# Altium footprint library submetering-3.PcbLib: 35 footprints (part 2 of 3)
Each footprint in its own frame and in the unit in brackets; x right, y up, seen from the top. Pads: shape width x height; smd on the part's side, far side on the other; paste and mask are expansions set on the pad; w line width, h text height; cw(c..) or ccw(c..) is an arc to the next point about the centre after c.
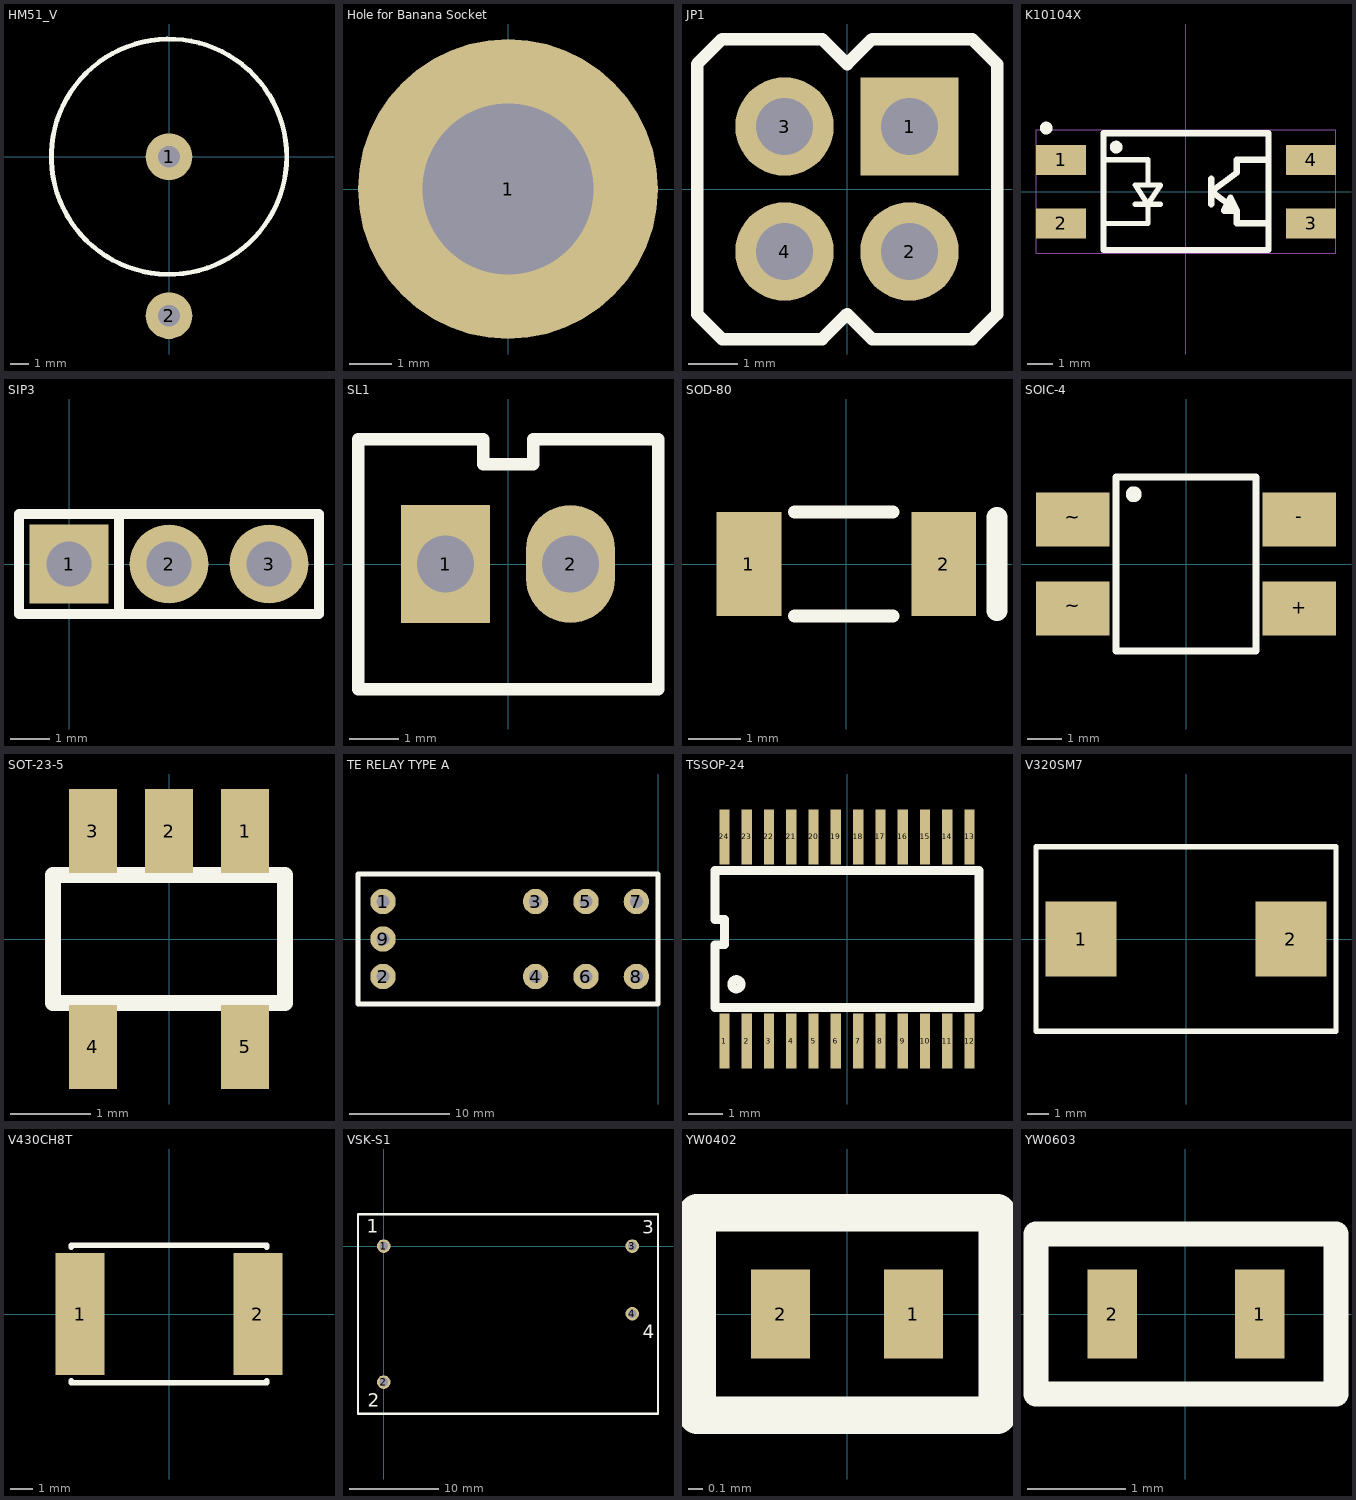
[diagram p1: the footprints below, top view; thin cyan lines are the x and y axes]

## HM51_V [mm] "HM51 Insductors (vertical)"
pads (2):
  round 2.5 hole 1.15: 1(0,0) 2(0,-8.5)
TopOverlay:
  circle w0.254: c0,0 r6.294

## Hole for Banana Socket [mm] "Hole for Banana Socket"
pads (1):
  round 7 hole 4: 1(0,0)

## JP1 [mm]
pads (4):
  rect 2x2 hole 1.15: 1(1.27,1.27)
  round 2 hole 1.15: 2(1.27,-1.27) 3(-1.27,1.27) 4(-1.27,-1.27)
TopOverlay:
  lines w0.254: -3.048,-2.54 -3.048,2.54 -2.54,3.048 -0.508,3.048 0,2.54 0.508,3.048 2.54,3.048 3.048,2.54 3.048,-2.54 2.54,-3.048 0.508,-3.048 0,-2.54 -0.508,-3.048 -2.54,-3.048 -3.048,-2.54

## K10104X [mm] "K10104X"
pads (4):
  rect 2x1.2 smd: 1(-4.997,1.283) 2(-4.997,-1.257) 3(5.003,-1.257) 4(5.003,1.283)
TopOverlay:
  circle w0.254: c-5.585,2.553 r0.127
  circle w0.254: c-2.791,1.791 r0.127
  lines w0.203: -3.299,-1.257 -1.521,-1.257 -1.521,-0.495 ; -3.299,1.283 -1.521,1.283 -1.521,0.267 ; -2.029,-0.495 -1.013,-0.495 ; -1.521,-0.495 -1.013,0.267 -2.029,0.267 -1.521,-0.495
  lines w0.254: 1.019,-0.495 1.019,0.521 ; 3.305,-1.257 2.035,-1.257 2.035,-0.749 ; 3.305,1.283 2.035,1.283 2.035,0.775 1.019,0.013 2.035,-0.749 ; 2.035,-0.749 1.781,-0.241 1.527,-0.749 2.035,-0.749 ; -3.299,-2.324 3.305,-2.324 3.305,2.349 -3.299,2.349 -3.299,-2.324
Mechanical 18:
  lines w0.025: -5.991,-2.451 5.998,-2.451 5.998,2.476 -5.991,2.476 -5.991,-2.451

## SIP3 [mm]
pads (3):
  rect 2x2 hole 1.15: 1(0,0)
  round 2 hole 1.15: 2(2.54,0) 3(5.08,0)
TopOverlay:
  lines w0.254: 1.27,-1.27 1.27,1.27 ; -1.27,-1.27 6.35,-1.27 6.35,1.27 -1.27,1.27 -1.27,-1.27

## SL1 [mm]
pads (2):
  rect 1.8x2.4 hole 1.15: 1(-1.27,0)
  oval 1.8x2.4 hole 1.15: 2(1.27,0)
TopOverlay:
  lines w0.254: -3.048,-2.54 3.048,-2.54 3.048,2.032 3.048,2.54 0.508,2.54 0.508,2.032 -0.508,2.032 -0.508,2.54 -3.048,2.54 -3.048,2.032 -3.048,-2.54

## SOD-80 [mm]
pads (2):
  rect 1.25x2 smd: 1(-1.875,0) 2(1.875,0)
TopOverlay:
  lines w0.254: -1,-1 0.9,-1 ; -1,1 0.9,1
  lines w0.4: 2.9,-0.9 2.9,0.9
3D body: height 0.69, standoff -0.7, extent -1.28,-0.697 1.28,0.7
3D body: height 0.79, standoff -0.8, extent 1.28,-0.8 1.75,0.797
3D body: height 0.79, standoff -0.8, extent -1.7,-0.798 -1.23,0.798
3D body: height 0.69, standoff -0.7, extent 1,-0.697 1.2,0.7

## SOIC-4 [mm] "SOIC-4"
height 2.65
pads (4):
  rect 2.1x1.55 smd: +(3.25,-1.27) -(3.25,1.27) ~(-3.25,-1.27) ~(-3.25,1.27)
TopOverlay:
  circle w0.254: c-1.5,2 r0.1
  lines w0.2: -2,-2.5 2,-2.5 2,2.5 -2,2.5 -2,0 -2,-2.5

## SOT-23-5 [mm]
pads (5):
  rect 0.6x1.05 smd: 1(0.95,1.35) 2(0,1.35) 3(-0.95,1.35) 4(-0.95,-1.35) 5(0.95,-1.35)
TopOverlay:
  lines w0.203: -1.45,-0.8 1.45,-0.8 1.45,0.8 -1.45,0.8 -1.45,-0.8

## TE RELAY TYPE A [mm] "TE Relay type A footprint"
height 15.7
pads (9):
  round 2.54 hole 1.3: 1(-27.5,3.75) 2(-27.5,-3.75) 3(-12.24,3.75) 4(-12.24,-3.75) 5(-7.2,3.75) 6(-7.2,-3.75) 7(-2.16,3.75) 8(-2.16,-3.75) 9(-27.5,0)
TopOverlay:
  lines w0.5: -30,-6.5 -30,6.5 0,6.5 0,-6.5 -30,-6.5
Mechanical5:
  text ".Designator" at -23.6,-0.5 h1.02
3D body: height 15.7, standoff 0, extent -30.25,-6.75 0.25,6.75
3D body: height 15.7, standoff 0, extent -29.999,-6.499 -0.001,6.499
3D body: height 15.7, standoff 0, extent -30.25,-6.75 0.25,6.75
3D body: height 15.7, standoff 0, extent -28.872,-5.122 -0.788,5.122

## TSSOP-24 [mm] "TSSOP-24 (IPW)"
pads (24):
  rect 0.3x1.6 smd: 1(-3.575,-2.98) 2(-2.925,-2.98) 3(-2.275,-2.98) 4(-1.625,-2.98) 5(-0.975,-2.98) 6(-0.325,-2.98) 7(0.325,-2.98) 8(0.975,-2.98) 9(1.625,-2.98) 10(2.275,-2.98) 11(2.925,-2.98) 12(3.575,-2.98) 13(3.575,2.98) 14(2.925,2.98) 15(2.275,2.98) 16(1.625,2.98) 17(0.975,2.98) 18(0.325,2.98) 19(-0.325,2.98) 20(-0.975,2.98) 21(-1.625,2.98) 22(-2.275,2.98) 23(-2.925,2.98) 24(-3.575,2.98)
TopOverlay:
  circle w0.254: c-3.226,-1.321 r0.137
  lines w0.254: -3.85,-2 -3.85,-0.167 -3.571,-0.167 -3.571,0.57 -3.85,0.57 -3.85,2 3.85,2 3.85,-2 -3.85,-2

## V320SM7 [mm] "SMD MOV"
height 6
pads (2):
  rect 3.3x3.5 smd: 1(-4.9,0) 2(4.9,0)
TopOverlay:
  lines w0.254: -7,-4.3 -7,4.3 7,4.3 7,-4.3 -7,-4.3
3D body: height 6, standoff 0.3, extent -5.7,-4.1 5.7,4
3D body: height 3, standoff 0, extent -6,-1.5 -5.7,1.5
3D body: height 3, standoff 0, extent 5.7,-1.5 6,1.5

## V430CH8T [mm] "MOV"
height 2.03
pads (2):
  rect 2.21x5.5 smd: 1(-4,0) 2(4,0)
TopOverlay:
  lines w0.254: -4.4,-3 -4.4,-3.1 4.4,-3.1 4.4,-3 ; -4.4,3 -4.4,3.1 4.4,3.1 4.4,3
Mechanical5:
  text ".Designator" at 0,0 h1.02
3D body: height 2.03, standoff 0, extent 3.3,-2.5 4.1,2.5
3D body: height 2.03, standoff 0, extent -4.1,-2.5 -3.3,2.5
3D body: height 2.03, standoff 0, extent -3.3,-2.5 3.3,2.5

## VSK-S1 [mil] "On board block power supply"
height 708.66
pads (4):
  round 60 hole 39.37: 1(0,0) 2(0,-603.31) 3(1102.36,0) 4(1102.36,-300)
TopOverlay:
  lines w10: -114.17,141.73 -114.17,-744.09 1216.54,-744.09 1216.54,141.73 ; -112.2,141.73 1214.57,141.73
  text "1" at -74.8,59.06 h60
  text "2" at -70.87,-712.6 h60
  text "3" at 1145.67,55.12 h60
  text "4" at 1149.61,-409.45 h60
3D body: height 708.66, standoff 0, extent -98.43,-720.47 1192.91,118.11

## YW0402 [mm]
pads (2):
  rect 0.4x0.6 smd: 1(0.45,0) 2(-0.45,0)
TopOverlay:
  lines w0.254: -1.016,-0.686 -1.016,0.686 1.016,0.686 1.016,-0.686 -1.016,-0.686

## YW0603 [mm]
pads (2):
  rect 0.5x0.9 smd: 1(0.758,0) 2(-0.742,0)
TopOverlay:
  lines w0.254: -1.516,-0.813 -1.516,0.813 1.532,0.813 1.532,-0.813 -1.516,-0.813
